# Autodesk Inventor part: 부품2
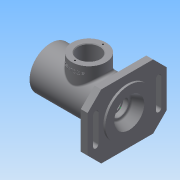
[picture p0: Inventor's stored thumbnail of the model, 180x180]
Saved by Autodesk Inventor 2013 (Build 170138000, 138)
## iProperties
Created: 2017-10
Part Number: 부품2
Material: 일반
Document SubType Name: Modeling
Designer: Windows7
Density: 1 g/cm^3
Author: Windows7
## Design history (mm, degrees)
sketch "스케치1"
  geometry: L1 (-57.5, 0)-(57.5, 0); L2 (-57.5, 21)-(-57.5, 31); L3 (-57.5, 31)-(57.5, 31); L4 (57.5, 31)-(57.5, 16); L5 (36.2, 12.5)-(36.2, 10); L6 (36.2, 10)-(33.5, 10); L7 (33.5, 10)-(33.5, 16.5); L8 (33.5, 16.5)-(28.5, 16.5); L9 (28.5, 16.5)-(28.5, 17.5); L10 (28.5, 17.5)-(17.5, 17.5); L11 (17.5, 17.5)-(17.5, 26); L12 (17.5, 26)-(-20.5, 26); L13 (-20.5, 26)-(-20.5, 17.5); L14 (-20.5, 17.5)-(-31.5, 17.5); L15 (-31.5, 17.5)-(-31.5, 18.5); L16 (-31.5, 18.5)-(-33.25, 18.5); L17 (-33.25, 18.5)-(-33.25, 17.5); L18 (-33.25, 17.5)-(-36.5, 17.5); L19 (-36.5, 17.5)-(-36.5, 20); L20 (-36.5, 20)-(-45.5, 20); L21 (-45.5, 20)-(-45.5, 24); L22 (-45.5, 24)-(-48.5, 24); L23 (-48.5, 24)-(-48.5, 21); L24 (-48.5, 21)-(-57.5, 21); L25 (36.2, 12.5)-(43.5, 12.5); L26 (43.5, 12.5)-(43.5, 16); L27 (43.5, 16)-(57.5, 16); 2 further points
  constraints: 54 end point, 21 parallel, 4 perpendicular, 2 vertical alignment, 1 coincident, 1 horizontal, 1 midpoint, 1 vertical
  dimensions: "d0" = 115 distance of L1.start L1.end; "d2" = 42 diameter of L24 L1; "d3" = 48 diameter of L22 L1; "d4" = 40 diameter of L20 L1; "d5" = 35 diameter of L18 L1; "d6" = 37 diameter of L16 L1; "d7" = 35 diameter of L14 L1; "d9" = 35 diameter of L10 L1; "d10" = 33 diameter of L8 L1; "d11" = 20 diameter of L6 L1; "d14" = 12 distance between parallel lines of L2 L21; "d15" = 3 distance between parallel lines of L21 L23; "d16" = 21 distance between parallel lines of L2 L19; "d18" = 38 distance between parallel lines of L11 L13; "d22" = 11 distance between parallel lines of L15 L13; "d25" = 11 distance between parallel lines of L11 L9; "d26" = 5 distance between parallel lines of L9 L7; "d31" = 62 diameter of L3 L1; "d32" = 2.7 distance between parallel lines of L7 L5; "d34" = 25 diameter of L25 L1; "d35" = 7.3 distance between parallel lines of L5 L26; "d36" = 32 diameter of L27 L1; "d118" = 26 distance between parallel lines of L2 L15; "d119" = 1.75 distance between parallel lines of L15 L17; "d123" = 52 diameter of L12 L1
revolve "회전1" sketch "스케치1" stored, may be unused: angle "d37" = 90 deg
node "작업 평면1"
sketch "스케치2"
  geometry: 1 further point
sketch "스케치3"
  geometry: L1 (-58, 47)-(58, 47); L2 (58, 47)-(58, -47); L3 (58, -47)-(-58, -47); L4 (-58, -47)-(-58, 47); L5 (-58, 47)-(58, -47); C1 r 31 at (0, 0) reference; C2 r 16 at (0, 0) reference; 2 further points
  constraints: 10 end point, 2 parallel, 1 coincident, 1 horizontal, 1 midpoint, 1 perpendicular
  dimensions: "d43" = 116 distance between parallel lines of L2 L4; "d45" = 94 distance between parallel lines of L3 L1
extrude "돌출1" join sketch "스케치3" distance "d46" = 10; taper "d47" = 0 deg
chamfer "모따기1" distance "d48" = 20; stored, may be unused: second distance "d49" = 2, angle "d50" = 45 deg
sketch "스케치4"
  geometry: L1 (-38, -47)-(38, -47) reference; L2 (-50, 20)-(-50, -20); L3 (-42, -20)-(-42, 20); C1 r 31 at (0, 0) reference; A1 r 4 centre (-46, -20) between (-50, -20) and (-42, -20); A2 r 4 centre (-46, 20) between (-42, 20) and (-50, 20)
  constraints: 4 end point, 4 point on circle, 4 tangent, 2 centre point, 1 parallel, 1 perpendicular
  dimensions: "d51" = 46 horizontal distance of C1.centre A1.centre; "d52" = 40 distance of A2.centre A1.centre; "d53" = 20 vertical distance of A1.centre C1.centre; "d55" = 4 radius of A2
extrude "돌출2" cut sketch "스케치4" stored distance "d56" = 10; taper "d57" = 0 deg
sketch "스케치5"
  geometry: C1 r 31 at (0, 0) reference; C2 r 35 at (0, 0)
  constraints: 1 centre point, 1 coincident
  dimensions: "d58" = 70 diameter of C2
extrude "돌출3" join sketch "스케치5" distance "d60" = 3; taper "d61" = 0 deg
node "작업 평면2"
sketch "스케치6"
  geometry: L1 (57.5, 31)-(57.5, -31) reference; C1 r 25 at (1.5, 0); 2 further points
  constraints: 1 centre point, 1 coincident, 1 horizontal alignment, 1 midpoint
  dimensions: "d63" = 50 diameter of C1; "d121" = 31 distance edge to line of C1 L1
extrude "돌출4" join sketch "스케치6" stored distance "d65" = 3; taper "d66" = 0 deg
sketch "스케치7"
  geometry: C1 r 25 at (0, 0) reference
hole "구멍1" sketch "스케치7" at (0, 0) diameter "d67" = 32; stored, may be unused: countersink angle "d71" = 90 deg, drill point angle "d73" = 0 deg; dims "d68" = 6, "d69" = 32, "d70" = 2, "d72" = 8
chamfer "모따기2" distance "d74" = 1; stored, may be unused: second distance "d75" = 2, angle "d76" = 45 deg
feature "스레드1" dims "d77" = 10, "d78" = 0
chamfer "모따기3" distance "d79" = 1; stored, may be unused: second distance "d80" = 2, angle "d81" = 45 deg
chamfer "모따기4" distance "d82" = 1; stored, may be unused: second distance "d83" = 2, angle "d84" = 45 deg
chamfer "모따기5" distance "d85" = 1; stored, may be unused: second distance "d86" = 2, angle "d87" = 45 deg
chamfer "모따기6" distance "d88" = 0.7; stored, may be unused: second distance "d89" = 2, angle "d90" = 30 deg
fillet "모깎기1" dims "d91" = 0.3
fillet "모깎기2" dims "d92" = 0.3
fillet "모깎기3" dims "d93" = 3
fillet "모깎기4" dims "d94" = 3
sketch "스케치8"
  geometry: L1 (-18.5, 47)-(-17.5, 46) reference; L2 (-17.5, 46)-(-17.5, 26) reference; L3 (-20.5, 23)-(-20.5, 18.5) reference; L4 (-20.5, 18.5)-(-21.5, 17.5) reference; L5 (-21.5, 17.5)-(-31.5, 17.5) reference; L6 (-31.5, 17.5)-(-31.5, 18.5) reference; L7 (-31.5, 18.5)-(-33.25, 18.5) reference; L8 (-33.25, 18.5)-(-33.25, 17.5) reference; L9 (-33.25, 17.5)-(-36.5, 17.5) reference; L10 (-36.5, 17.5)-(-36.5, 20) reference; L11 (-36.5, 20)-(-45.5, 20) reference; L12 (-45.5, 20)-(-45.5, 24) reference; L13 (-45.5, 24)-(-48.5, 24) reference; L14 (-48.5, 24)-(-48.5, 21) reference; L15 (-48.5, 21)-(-56.5, 21) reference; L16 (-56.5, 21)-(-57.5, 22) reference; L17 (-57.5, 22)-(-57.5, 31) reference; L18 (-57.5, 31)-(-26.5, 31) reference; L19 (-26.5, 31)-(-26.5, 47) reference; L20 (-26.5, 47)-(-18.5, 47) reference; L21 (57.5, -35)-(54.5, -35) reference; L22 (54.5, -35)-(54.5, -47) reference; L23 (54.5, -47)-(44.5, -47) reference; L24 (44.5, -47)-(44.5, -31) reference; L25 (44.5, -31)-(-57.5, -31) reference; L26 (-57.5, -31)-(-57.5, -22) reference; L27 (-57.5, -22)-(-56.5, -21) reference; L28 (-56.5, -21)-(-48.5, -21) reference; L29 (-48.5, -21)-(-48.5, -24) reference; L30 (-48.5, -24)-(-45.5, -24) reference; L31 (-45.5, -24)-(-45.5, -20) reference; L32 (-45.5, -20)-(-36.5, -20) reference; L33 (-36.5, -20)-(-36.5, -17.5) reference; L34 (-36.5, -17.5)-(-33.25, -17.5) reference; L35 (-33.25, -17.5)-(-33.25, -18.5) reference; L36 (-33.25, -18.5)-(-31.5, -18.5) reference; L37 (-31.5, -18.5)-(-31.5, -17.5) reference; L38 (-31.5, -17.5)-(-21.5, -17.5) reference; L39 (-21.5, -17.5)-(-20.5, -18.5) reference; L40 (-20.5, -18.5)-(-20.5, -23) reference; L41 (-17.5, -26)-(14.5, -26) reference; L42 (17.5, -23)-(17.5, -18.5) reference; L43 (17.5, -18.5)-(18.5, -17.5) reference; L44 (18.5, -17.5)-(28.2, -17.5) reference; L45 (28.5, -17.2)-(28.5, -16.5) reference; L46 (28.5, -16.5)-(30.5, -16.5) reference; L47 (33.5, -13.5)-(33.5, -10) reference; L48 (33.5, -10)-(36.2, -10) reference; L49 (36.2, -10)-(36.2, -12.2) reference; L50 (36.5, -12.5)-(42.8, -12.5) reference; L51 (42.8, -12.5)-(43.5, -12.904) reference; L52 (43.5, -12.904)-(43.5, -16) reference; L53 (43.5, -16)-(57.5, -16) reference; L54 (57.5, -16)-(57.5, -35) reference; L55 (54.5, 35)-(57.5, 35) reference; L56 (57.5, 35)-(57.5, 16) reference; L57 (57.5, 16)-(43.5, 16) reference; L58 (43.5, 16)-(43.5, 12.904) reference; L59 (43.5, 12.904)-(42.8, 12.5) reference; L60 (42.8, 12.5)-(36.5, 12.5) reference; L61 (36.2, 12.2)-(36.2, 10) reference; L62 (36.2, 10)-(33.5, 10) reference; L63 (33.5, 10)-(33.5, 13.5) reference; L64 (30.5, 16.5)-(28.5, 16.5) reference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; A1 r 3 centre (-17.5, 23) between (-17.5, 26) and (-20.5, 23) reference; A2 r 3 centre (-17.5, -23) between (-20.5, -23) and (-17.5, -26) reference; A3 r 3 centre (14.5, -23) between (14.5, -26) and (17.5, -23) reference; A4 r 0.3 centre (28.2, -17.2) between (28.2, -17.5) and (28.5, -17.2) reference; A5 r 3 centre (30.5, -13.5) between (30.5, -16.5) and (33.5, -13.5) reference; A6 r 0.3 centre (36.5, -12.2) between (36.2, -12.2) and (36.5, -12.5) reference; A7 r 0.3 centre (36.5, 12.2) between (36.5, 12.5) and (36.2, 12.2) reference; A8 r 3 centre (30.5, 13.5) between (33.5, 13.5) and (30.5, 16.5) reference; A9 r 0.3 centre (28.2, 17.2) between (28.5, 17.2) and (28.2, 17.5) reference; A10 r 3 centre (14.5, 23) between (17.5, 23) and (14.5, 26) reference; 2 further points
  constraints: 4 end point, 1 horizontal alignment, 1 midpoint, 1 perpendicular, 1 point on line
  dimensions: "d95" = 44 diameter of L78.end L77
revolve "회전2" sketch "스케치8" stored, may be unused: angle "d97" = 90 deg
fillet "모깎기5" dims "d98" = 3
sketch "스케치9" dims "d99" = 41
  geometry: C1 r 25 at (0, 0) reference; C2 r 17 at (0, 0) reference; 2 further points
  constraints: 2 vertical alignment, 1 coincident, 2 other
hole "구멍2" sketch "스케치9" at (0, 20.5) diameter "d101" = 2.459; stored, may be unused: countersink angle "d105" = 90 deg, drill point angle "d107" = 118 deg; dims "d102" = 6, "d103" = 32, "d104" = 2, "d106" = 8
node "작업 평면3"
sketch "스케치10"
  geometry: L1 (-25, 0)-(25, 0) reference; L2 (-56, -78)-(-56, -16) reference; 2 further points
  constraints: 1 other
  dimensions: "d111" = 10 distance from line of L1 point (0, -10); "d112" = 56 distance from line of L2 point (0, -10)
feature "엠보싱1" sketch "스케치10" dims "d0" = 115, "d2" = 42, "d3" = 48, "d4" = 40, "d5" = 35, "d6" = 37, "d7" = 35, "d9" = 35, "d10" = 33, "d11" = 20, "d14" = 12, "d15" = 3, "d16" = 21, "d18" = 38, "d22" = 11, "d25" = 11, "d26" = 5, "d31" = 62, "d32" = 2.7, "d34" = 25, "d35" = 7.3, "d36" = 32, "d113" = 0.5, "d114" = 0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
fillet "모깎기6" dims "d115" = 3
fillet "모깎기7" dims "d116" = 3
node "솔리드1"
mirror "대칭1"
pattern_circular "원형 패턴1" dims angle "d109" = 360 deg
node "절단 모서리 투영1"
node "절단 모서리 투영2"
other parameters: "d38" = -13, "d39" = 0.5, "d40" = 2, "d41" = 0, "d62" = 47
